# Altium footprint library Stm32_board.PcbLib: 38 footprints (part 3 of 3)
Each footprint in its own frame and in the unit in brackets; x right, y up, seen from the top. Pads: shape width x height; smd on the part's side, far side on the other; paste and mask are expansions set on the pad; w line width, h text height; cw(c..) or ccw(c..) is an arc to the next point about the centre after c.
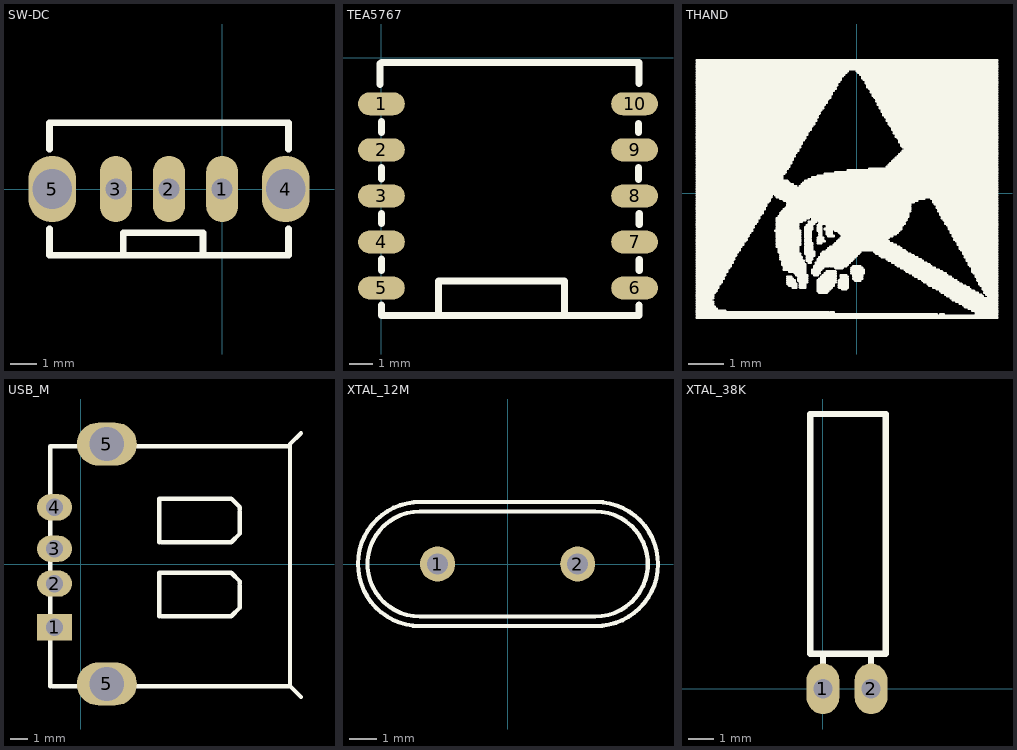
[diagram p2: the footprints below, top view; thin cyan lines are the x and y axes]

## SW-DC [mm]
pads (5):
  oval 1.2x2.5 hole 0.8: 1(0,0) 2(-2,0) 3(-4,0)
  oval 1.8x2.5 hole 1.5: 4(2.4,0) 5(-6.4,0)
Top Overlay:
  lines w0.254: -6.5,-1.5 -6.5,-2.5 2.5,-2.5 2.5,-1.5 ; -6.5,1.5 -6.5,2.5 2.5,2.5 2.5,1.5 ; -3.746,-2.5 -3.723,-2.477 -3.723,-1.651 -0.723,-1.651 -0.723,-2.5

## TEA5767 [mm]
pads (10):
  oval 2.032x1 smd: 1(0,-2) 2(0,-4) 3(0,-6) 4(0,-8) 5(0,-10) 6(11,-10) 7(11,-8) 8(11,-6) 9(11,-4) 10(11,-2)
Top Overlay:
  lines w0.305: -0.051,-1.168 -0.051,-0.251 0,-0.2 11.2,-0.2 11.2,-1.116 ; 0,-10.744 0,-11.2 11.2,-11.2 11.2,-10.746 ; 0,-9.246 0,-8.738 ; 0,-7.188 0,-6.756 ; 0,-5.258 0,-4.775 ; 0,-3.251 0,-2.769 ; 2.489,-11.2 2.489,-9.703 7.95,-9.703 7.95,-11.175 7.976,-11.2 ; 11.176,-5.283 11.176,-4.775 ; 11.176,-3.251 11.176,-2.845 ; 11.201,-9.246 11.201,-8.763 ; 11.201,-7.239 11.201,-6.756

## THAND [mil]
Top Overlay:
  drawing of 472 lines, arcs and shapes, not listed

## USB_M [mil]
pads (6):
  rect 80x60 hole 40: 1(-60,-145)
  oval 80x60 hole 40: 2(-60,-45) 3(-60,35) 4(-60,130)
  oval 137.79x98.42 hole 78.74: 5(60,-275) 5(60,275)
Top Overlay:
  lines w10: -70,-280 -70,270 480,270 ; -65,-280 480,-280 ; 180,-120 180,-20 345,-20 365,-40 365,-45 ; 180,50 180,150 345,150 365,130 365,125 ; 185,-120 345,-120 365,-100 365,-50 ; 185,50 345,50 365,70 365,120 ; 505,-305 480,-280 ; 505,300 480,275 480,270 ; 480,-280 480,270

## XTAL_12M [mil]
pads (2):
  round 50 hole 30: 1(-100,0) 2(100,0)
Top Overlay:
  lines w6: -125,-88.58 cw(c-125,0) -124.07,88.58 126,88.58 cw(c126,0) 125.09,-88.58 -125,-88.58 ; -125,-75 cw(c-125,0) -125,75 125,75 cw(c125,0) 125,-75 -125,-75

## XTAL_38K [mm]
pads (2):
  oval 1.3x2 hole 0.762: 1(0,0) 2(1.905,0)
Top Overlay:
  lines w0.254: 0,0 0,1.397 ; 1.905,0 1.905,1.397 ; -0.508,1.397 2.492,1.397 2.492,10.897 -0.508,10.897 -0.508,1.397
